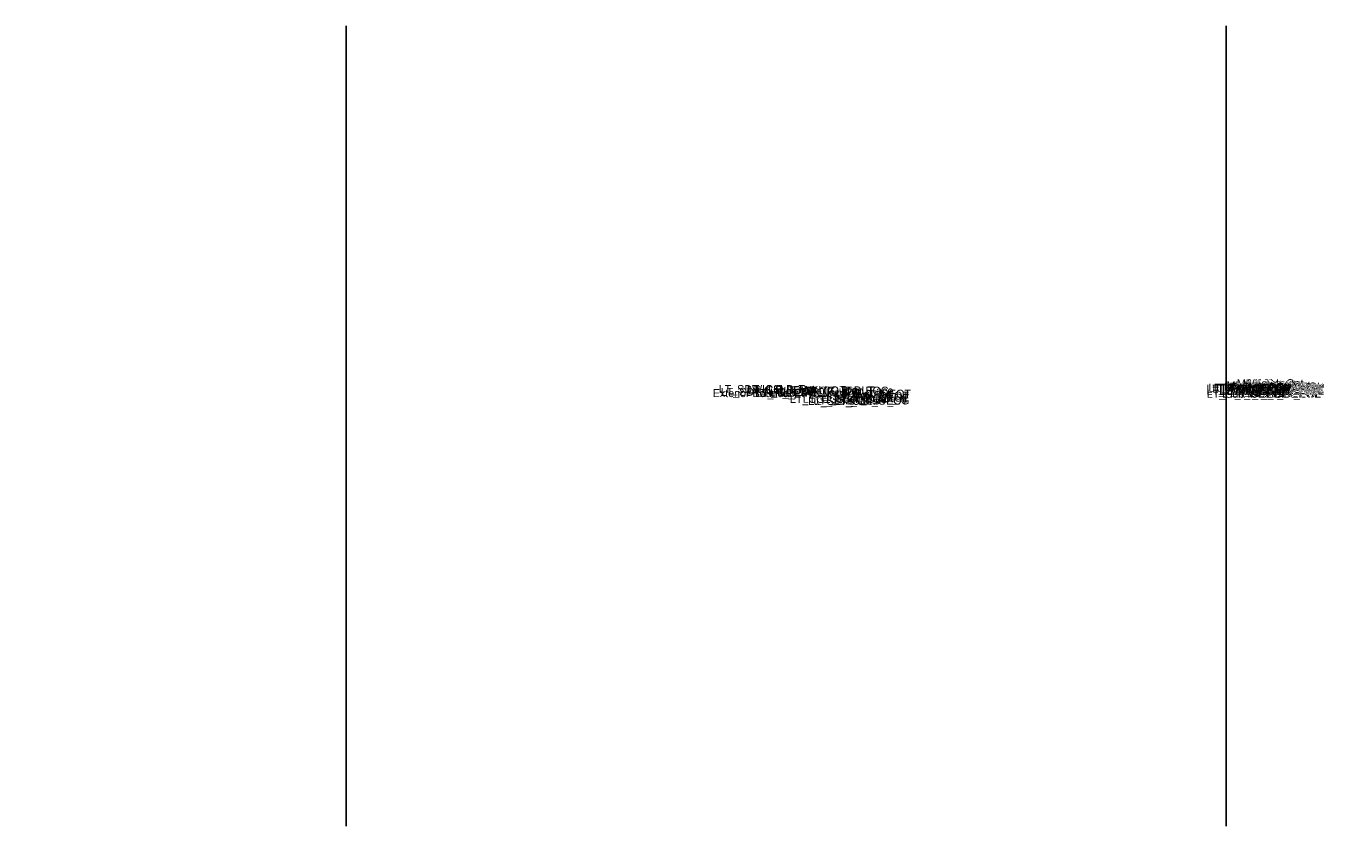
# Model space of a CAD drawing. Extents: x 0 to 6300, y -50 to 9550.
# Drawn here: x 3000 to 3162.2, y 5450 to 5550 of the extents above; entities that cross this region are included whole.
import ezdxf

# ---------------------------------------------------------------- set-up
doc = ezdxf.new("R2010")
doc.units = 0
for name, color, linetype in [('Default', 7, 'Continuous'), ('Prop XS Exc Vertical Line 1', 7, 'Continuous'), ('Prop XS Exc Vertical Line 2', 7, 'Continuous')]:
    doc.layers.add(name, color=color, linetype=linetype)

msp = doc.modelspace()

# ---------------------------------------------------------------- linework, layer by layer
at = {"layer": 'Prop XS Exc Vertical Line 1'}
msp.add_line((3040, 5550), (3040, 5450), dxfattribs=at)
at = {"layer": 'Prop XS Exc Vertical Line 2'}
msp.add_line((3150, 5550), (3150, 5450), dxfattribs=at)

# ---------------------------------------------------------------- texts
at = {"layer": 'Default'}
for s, height, p in [('Exterior Boundary', 1, (3085.83, 5503.61)), ('LT_SDWK_Out_Top', 1, (3086.58, 5504.11)), ('LT_SDWK_Out_Bot', 1, (3086.83, 5503.77)), ('LT_CSLP_Pnt', 1, (3090.1, 5504.11)), ('LT_Sub_Trench_Out_DLT', 1, (3090.22, 5503.96)), ('LT_Tie_Pt', 1, (3091.11, 5503.61)), ('LT_SDWK_In_Top', 1, (3092.74, 5504.01)), ('LT_SDWK_In_Bot', 1, (3092.99, 5503.67)), ('LT_CG_Top_BOC', 1, (3096.81, 5503.92)), ('LT_CG_Top_Face', 1, (3097.34, 5503.92)), ('LT_PV1_OEOT', 1, (3101.23, 5503.54)), ('LT_PV2_OEEOP', 1, (3147.54, 5504.15)), ('LT_PV3_OEEOP', 1, (3147.54, 5503.9)), ('LT_Sub_OEEOP', 1, (3147.58, 5503.53)), ('LT_PV1_OEEOP', 1, (3147.77, 5504.28)), ('LT_PV2_IEEOP', 1, (3148.3, 5504.15)), ('LT_PV1_IEEOP', 1, (3148.54, 5504.28)), ('LT_PV2_PGL1', 1, (3149.13, 5504.15)), ('LT_PV3_PGL1', 1, (3149.13, 5503.9)), ('LT_PV2_PGL', 1, (3149.51, 5504.15)), ('LT_PV4_PGL', 1, (3149.51, 5503.53)), ('LT_PV1_PGL', 1, (3149.75, 5504.4)), ('MI_Face In', 1, (3150.05, 5504.57)), ('MI_Bot In', 1, (3151.22, 5504.4)), ('MI_Top In', 1, (3151.34, 5504.82)), ('RT_PV2_OEEOP', 1, (3151.42, 5504.18)), ('RT_PV3_OEEOP', 1, (3151.42, 5503.93)), ('RT_Sub_OEEOP', 1, (3151.46, 5503.56)), ('RT_PV1_OEEOP', 1, (3151.66, 5504.31)), ('RT_PV2_IEEOP', 1, (3152.18, 5504.18)), ('RT_PV1_IEEOP', 1, (3152.42, 5504.31)), ('MI_Top Out', 1, (3152.6, 5504.85)), ('MI_Crown', 1, (3152.74, 5504.87)), ('MI_Face Out', 1, (3152.81, 5504.6)), ('RT_PV2_PGL1', 1, (3153.02, 5504.18)), ('RT_PV3_PGL1', 1, (3153.02, 5503.93)), ('RT_PV2_PGL', 1, (3153.4, 5504.18)), ('RT_PV4_PGL', 1, (3153.4, 5503.56)), ('RT_PV1_PGL', 1, (3153.63, 5504.43)), ('MI_Bot Out', 1, (3154, 5504.43)), ('LT_CG1_Shelf_Out', 1, (3095.48, 5502.89)), ('LT_CG_Bot_BOC', 1, (3097.09, 5502.9)), ('LT_Sub_OEOP', 1, (3097.77, 5502.64)), ('LT_CG_Top_Gut', 1, (3097.87, 5503.42)), ('LT_Sub_OEOT_CG', 1, (3098.44, 5502.7)), ('LT_PV2_OEOT', 1, (3100.99, 5503.29)), ('LT_PV3_OEOT', 1, (3100.99, 5503.04)), ('LT_Sub_OEOT', 1, (3101.04, 5502.66)), ('LT_CG_Bot_IE', 1, (3101.34, 5502.95)), ('-', 0.0001, (3000, 5500))]:
    msp.add_text(s, height=height, dxfattribs=at).set_placement(p)

doc.saveas('drawing.dxf')
